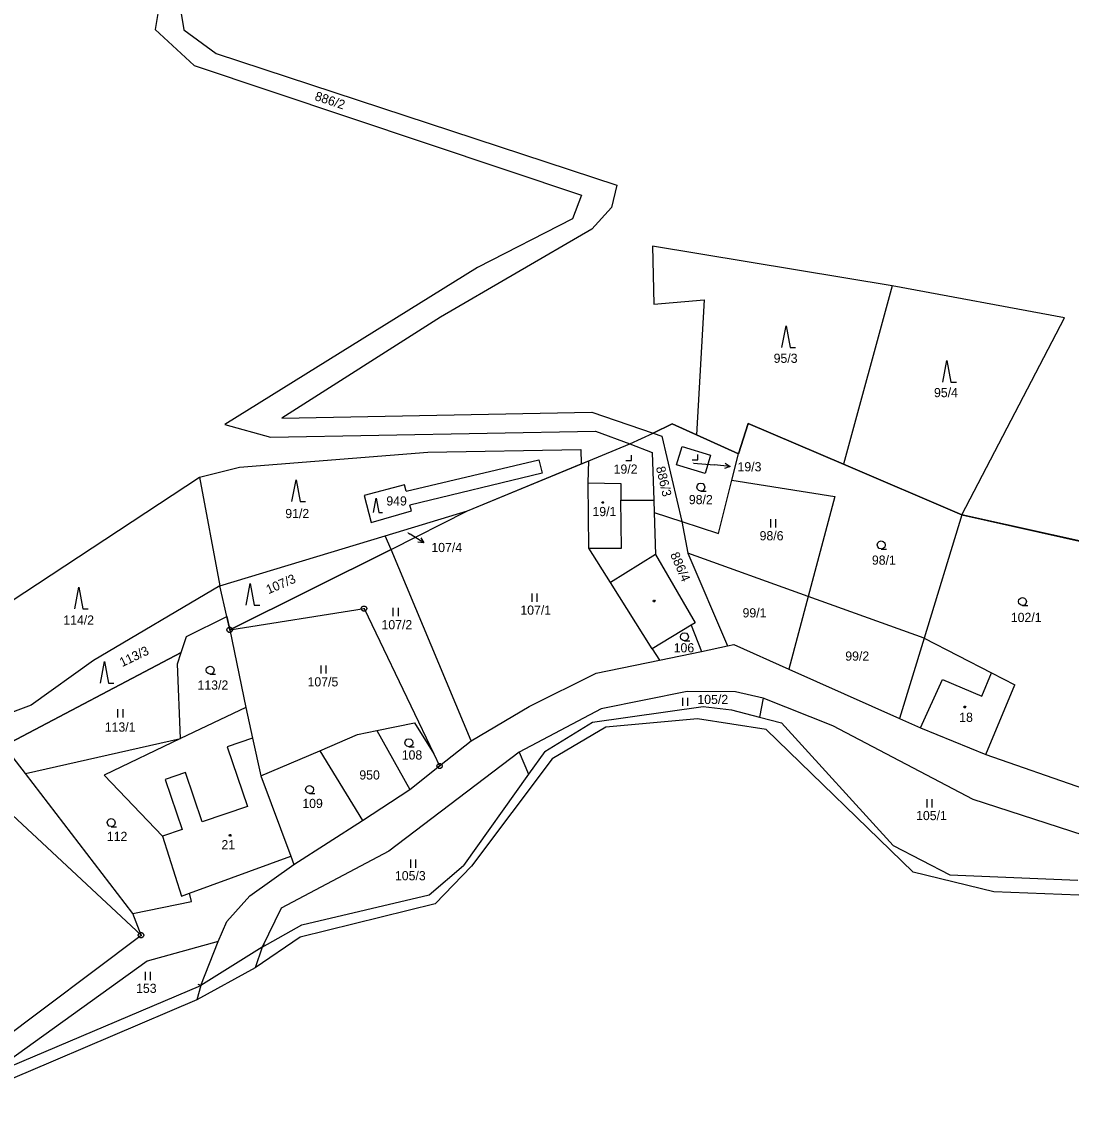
# Model space of a CAD drawing. Extents: x -580551 to -575069, y -1073031 to -1067931.
# Drawn here: x -576676.1 to -576481.9, y -1069876.2 to -1069674.8 of the extents above; entities that cross this region are included whole.
import ezdxf

# ---------------------------------------------------------------- set-up
doc = ezdxf.new("R2010")
doc.units = 0
for name, color, linetype in [('Druh pozemku', 7, 'Continuous'), ('Geodetické body', 7, 'Continuous'), ('Katastrální hranice', 7, 'Continuous'), ('Parcela', 7, 'Continuous'), ('Parcelní číslo', 7, 'Continuous'), ('Parcelní číslo_stavba', 7, 'Continuous'), ('Pomocná vrstva', 7, 'Continuous'), ('SR - hranice státu', 7, 'Continuous'), ('Vnitřní kresba', 7, 'Continuous'), ('Vrstva 26', 7, 'Continuous'), ('Vrstva 6', 7, 'Continuous')]:
    doc.layers.add(name, color=color, linetype=linetype)

msp = doc.modelspace()

# ---------------------------------------------------------------- linework, layer by layer
at = {"layer": 'Druh pozemku'}
for p, q in [((-576537.53, -1069766.84), (-576537.53, -1069768.34)), ((-576536.53, -1069768.34), (-576536.53, -1069766.84)), ((-576581.73, -1069780.59), (-576581.73, -1069782.09)), ((-576580.73, -1069782.09), (-576580.73, -1069780.59)), ((-576607.43, -1069783.24), (-576607.43, -1069784.74)), ((-576606.43, -1069784.74), (-576606.43, -1069783.24)), ((-576620.78, -1069793.89), (-576620.78, -1069795.39)), ((-576619.78, -1069795.39), (-576619.78, -1069793.89)), ((-576553.84, -1069799.85), (-576553.84, -1069801.35)), ((-576552.84, -1069801.35), (-576552.84, -1069799.85)), ((-576658.39, -1069802), (-576658.39, -1069803.5)), ((-576657.39, -1069803.5), (-576657.39, -1069802)), ((-576508.61, -1069818.65), (-576508.61, -1069820.15)), ((-576507.61, -1069820.15), (-576507.61, -1069818.65)), ((-576604.19, -1069829.8), (-576604.19, -1069831.3)), ((-576603.19, -1069831.3), (-576603.19, -1069829.8)), ((-576653.3, -1069850.6), (-576653.3, -1069852.1)), ((-576652.3, -1069852.1), (-576652.3, -1069850.6))]:
    msp.add_line(p, q, dxfattribs=at)
for points in [[(-576535.42, -1069735.03), (-576534.67, -1069731.03), (-576533.92, -1069735.03), (-576532.92, -1069735.03)], [(-576505.63, -1069741.44), (-576504.88, -1069737.44), (-576504.13, -1069741.44), (-576503.13, -1069741.44)], [(-576564.29, -1069755.94), (-576563.29, -1069755.94), (-576563.29, -1069754.94)], [(-576552.01, -1069755.82), (-576551.01, -1069755.82), (-576551.01, -1069754.82)], [(-576626.12, -1069763.52), (-576625.37, -1069759.52), (-576624.62, -1069763.52), (-576623.62, -1069763.52)], [(-576550.43, -1069761.62), (-576550.81, -1069761.52), (-576551.08, -1069761.25), (-576551.18, -1069760.88), (-576551.08, -1069760.51), (-576550.81, -1069760.24), (-576550.44, -1069760.14), (-576550.07, -1069760.24), (-576549.8, -1069760.51), (-576549.7, -1069760.89), (-576549.8, -1069761.27), (-576550.07, -1069761.54), (-576550.45, -1069761.64), (-576549.45, -1069761.64)], [(-576611.032, -1069765.58), (-576610.53, -1069762.9), (-576610.028, -1069765.58), (-576609.358, -1069765.58)], [(-576517.03, -1069772.33), (-576517.41, -1069772.23), (-576517.68, -1069771.96), (-576517.78, -1069771.59), (-576517.68, -1069771.22), (-576517.41, -1069770.95), (-576517.04, -1069770.85), (-576516.67, -1069770.95), (-576516.4, -1069771.22), (-576516.3, -1069771.6), (-576516.4, -1069771.98), (-576516.67, -1069772.25), (-576517.05, -1069772.35), (-576516.05, -1069772.35)], [(-576666.34, -1069783.39), (-576665.59, -1069779.39), (-576664.84, -1069783.39), (-576663.84, -1069783.39)], [(-576634.59, -1069782.74), (-576633.84, -1069778.74), (-576633.09, -1069782.74), (-576632.09, -1069782.74)], [(-576490.89, -1069782.79), (-576491.27, -1069782.69), (-576491.54, -1069782.42), (-576491.64, -1069782.05), (-576491.54, -1069781.68), (-576491.27, -1069781.41), (-576490.9, -1069781.31), (-576490.53, -1069781.41), (-576490.26, -1069781.68), (-576490.16, -1069782.06), (-576490.26, -1069782.44), (-576490.53, -1069782.71), (-576490.91, -1069782.81), (-576489.91, -1069782.81)], [(-576553.46, -1069789.31), (-576553.84, -1069789.21), (-576554.11, -1069788.94), (-576554.21, -1069788.57), (-576554.11, -1069788.2), (-576553.84, -1069787.93), (-576553.47, -1069787.83), (-576553.1, -1069787.93), (-576552.83, -1069788.2), (-576552.73, -1069788.58), (-576552.83, -1069788.96), (-576553.1, -1069789.23), (-576553.48, -1069789.33), (-576552.48, -1069789.33)], [(-576661.58, -1069797.17), (-576660.83, -1069793.17), (-576660.08, -1069797.17), (-576659.08, -1069797.17)], [(-576641.26, -1069795.49), (-576641.64, -1069795.39), (-576641.91, -1069795.12), (-576642.01, -1069794.75), (-576641.91, -1069794.38), (-576641.64, -1069794.11), (-576641.27, -1069794.01), (-576640.9, -1069794.11), (-576640.63, -1069794.38), (-576640.53, -1069794.76), (-576640.63, -1069795.14), (-576640.9, -1069795.41), (-576641.28, -1069795.51), (-576640.28, -1069795.51)], [(-576604.45, -1069808.92), (-576604.83, -1069808.82), (-576605.1, -1069808.55), (-576605.2, -1069808.18), (-576605.1, -1069807.81), (-576604.83, -1069807.54), (-576604.46, -1069807.44), (-576604.09, -1069807.54), (-576603.82, -1069807.81), (-576603.72, -1069808.19), (-576603.82, -1069808.57), (-576604.09, -1069808.84), (-576604.47, -1069808.94), (-576603.47, -1069808.94)], [(-576622.85, -1069817.58), (-576623.23, -1069817.48), (-576623.5, -1069817.21), (-576623.6, -1069816.84), (-576623.5, -1069816.47), (-576623.23, -1069816.2), (-576622.86, -1069816.1), (-576622.49, -1069816.2), (-576622.22, -1069816.47), (-576622.12, -1069816.85), (-576622.22, -1069817.23), (-576622.49, -1069817.5), (-576622.87, -1069817.6), (-576621.87, -1069817.6)], [(-576659.57, -1069823.71), (-576659.95, -1069823.61), (-576660.22, -1069823.34), (-576660.32, -1069822.97), (-576660.22, -1069822.6), (-576659.95, -1069822.33), (-576659.58, -1069822.23), (-576659.21, -1069822.33), (-576658.94, -1069822.6), (-576658.84, -1069822.98), (-576658.94, -1069823.36), (-576659.21, -1069823.63), (-576659.59, -1069823.73), (-576658.59, -1069823.73)]]:
    msp.add_lwpolyline(points, dxfattribs=at)
for points in [[(-576568.5, -1069763.58), (-576568.41, -1069763.73), (-576568.5, -1069763.88), (-576568.68, -1069763.88), (-576568.77, -1069763.73), (-576568.68, -1069763.58)], [(-576558.99, -1069781.83), (-576558.9, -1069781.98), (-576558.99, -1069782.13), (-576559.17, -1069782.13), (-576559.26, -1069781.98), (-576559.17, -1069781.83)], [(-576501.49, -1069801.42), (-576501.4, -1069801.57), (-576501.49, -1069801.72), (-576501.67, -1069801.72), (-576501.76, -1069801.57), (-576501.67, -1069801.42)], [(-576637.49, -1069825.15), (-576637.4, -1069825.3), (-576637.49, -1069825.45), (-576637.67, -1069825.45), (-576637.76, -1069825.3), (-576637.67, -1069825.15)]]:
    msp.add_lwpolyline(points, close=True, dxfattribs=at)
at = {"layer": 'Geodetické body'}
for p, q in [((-576612.9, -1069783.36), (-576612.66, -1069783.36)), ((-576637.77, -1069787.3), (-576637.53, -1069787.3)), ((-576598.92, -1069812.48), (-576598.68, -1069812.48)), ((-576654.17, -1069843.8), (-576653.93, -1069843.8))]:
    msp.add_line(p, q, dxfattribs=at)
for points in [[(-576612.63, -1069782.88), (-576612.38, -1069783.06), (-576612.28, -1069783.35), (-576612.38, -1069783.64), (-576612.63, -1069783.82), (-576612.94, -1069783.82), (-576613.19, -1069783.64), (-576613.29, -1069783.35), (-576613.19, -1069783.06), (-576612.94, -1069782.88)], [(-576637.5, -1069786.82), (-576637.25, -1069787), (-576637.15, -1069787.29), (-576637.25, -1069787.58), (-576637.5, -1069787.76), (-576637.81, -1069787.76), (-576638.06, -1069787.58), (-576638.16, -1069787.29), (-576638.06, -1069787), (-576637.81, -1069786.82)], [(-576598.65, -1069812), (-576598.4, -1069812.18), (-576598.3, -1069812.47), (-576598.4, -1069812.76), (-576598.65, -1069812.94), (-576598.96, -1069812.94), (-576599.21, -1069812.76), (-576599.31, -1069812.47), (-576599.21, -1069812.18), (-576598.96, -1069812)], [(-576653.9, -1069843.32), (-576653.65, -1069843.5), (-576653.55, -1069843.79), (-576653.65, -1069844.08), (-576653.9, -1069844.26), (-576654.21, -1069844.26), (-576654.46, -1069844.08), (-576654.56, -1069843.79), (-576654.46, -1069843.5), (-576654.21, -1069843.32)]]:
    msp.add_lwpolyline(points, close=True, dxfattribs=at)
at = {"layer": 'Katastrální hranice'}
for p, q in [((-576551.03, -1069803.75), (-576568.02, -1069805.29)), ((-576538.37, -1069805.74), (-576551.03, -1069803.75)), ((-576568.02, -1069805.29), (-576577.93, -1069811.18)), ((-576511.13, -1069832.12), (-576538.37, -1069805.74)), ((-576577.93, -1069811.18), (-576592.88, -1069831.04)), ((-576592.88, -1069831.04), (-576599.63, -1069837.99)), ((-576496.21, -1069835.74), (-576511.13, -1069832.12)), ((-576476.91, -1069836.55), (-576496.21, -1069835.74)), ((-576599.63, -1069837.99), (-576624.59, -1069844.18)), ((-576624.59, -1069844.18), (-576632.96, -1069849.85)), ((-576632.96, -1069849.85), (-576643.76, -1069855.73)), ((-576643.76, -1069855.73), (-576674.95, -1069869.1)), ((-576674.95, -1069869.1), (-576691.8, -1069876.18))]:
    msp.add_line(p, q, dxfattribs=at)
at = {"layer": 'Parcela'}
for p, q in [((-576647.31, -1069651.23), (-576651.43, -1069676.21)), ((-576647.17, -1069669.99), (-576646.13, -1069676.24)), ((-576651.43, -1069676.21), (-576644.23, -1069682.85)), ((-576646.13, -1069676.24), (-576640.16, -1069680.67)), ((-576640.16, -1069680.67), (-576565.99, -1069705.03)), ((-576644.23, -1069682.85), (-576572.5, -1069706.89)), ((-576565.99, -1069705.03), (-576566.97, -1069709.17)), ((-576572.5, -1069706.89), (-576574.2, -1069711.27)), ((-576566.97, -1069709.17), (-576570.63, -1069713.15)), ((-576574.2, -1069711.27), (-576591.75, -1069720.23)), ((-576570.63, -1069713.15), (-576598.6, -1069729.46)), ((-576591.75, -1069720.23), (-576638.57, -1069749.29)), ((-576598.6, -1069729.46), (-576627.99, -1069748.15)), ((-576627.99, -1069748.15), (-576570.63, -1069747)), ((-576570.63, -1069747), (-576559.28, -1069750.92)), ((-576638.57, -1069749.29), (-576630.1, -1069751.65)), ((-576555.75, -1069749.15), (-576559.28, -1069750.92)), ((-576551.25, -1069751.2), (-576555.75, -1069749.15)), ((-576541.66, -1069749.1), (-576543.46, -1069754.74)), ((-576524, -1069756.64), (-576541.66, -1069749.1)), ((-576630.1, -1069751.65), (-576569.94, -1069750.52)), ((-576569.94, -1069750.52), (-576563.6, -1069752.9)), ((-576563.6, -1069752.9), (-576559.28, -1069750.92)), ((-576559.28, -1069750.92), (-576557.63, -1069751.47)), ((-576557.63, -1069751.47), (-576553.98, -1069767.25)), ((-576543.46, -1069754.74), (-576551.25, -1069751.2)), ((-576571.19, -1069756.02), (-576563.6, -1069752.9)), ((-576563.6, -1069752.9), (-576559.45, -1069754.48)), ((-576554.93, -1069756.79), (-576553.91, -1069753.35)), ((-576553.91, -1069753.35), (-576548.66, -1069754.94)), ((-576559.45, -1069754.48), (-576559.15, -1069763.27)), ((-576548.66, -1069754.94), (-576549.61, -1069758.38)), ((-576544.68, -1069759.61), (-576543.46, -1069754.74)), ((-576604.99, -1069761.66), (-576580.4, -1069755.83)), ((-576593.62, -1069765.25), (-576572.58, -1069756.59)), ((-576580.4, -1069755.83), (-576579.83, -1069758.3)), ((-576572.58, -1069756.59), (-576571.19, -1069756.02)), ((-576571.3, -1069760.08), (-576571.19, -1069756.02)), ((-576549.61, -1069758.38), (-576554.93, -1069756.79)), ((-576502.1, -1069766), (-576524, -1069756.64)), ((-576694.77, -1069792.96), (-576643.26, -1069759.05)), ((-576643.26, -1069759.05), (-576639.47, -1069779.16)), ((-576579.83, -1069758.3), (-576604.29, -1069764.24)), ((-576547.14, -1069769.46), (-576544.68, -1069759.61)), ((-576544.68, -1069759.61), (-576525.62, -1069762.59)), ((-576605.31, -1069760.48), (-576612.77, -1069762.42)), ((-576604.99, -1069761.66), (-576605.31, -1069760.48)), ((-576571.3, -1069760.08), (-576565.25, -1069760.21)), ((-576571.16, -1069772.17), (-576571.3, -1069760.08)), ((-576565.25, -1069760.21), (-576565.22, -1069763.28)), ((-576612.77, -1069762.42), (-576611.45, -1069767.46)), ((-576565.22, -1069763.28), (-576559.15, -1069763.27)), ((-576559.15, -1069763.27), (-576559.07, -1069765.6)), ((-576525.62, -1069762.59), (-576530.55, -1069781.12)), ((-576611.45, -1069767.46), (-576604.01, -1069765.29)), ((-576608.86, -1069769.87), (-576593.62, -1069765.25)), ((-576607.77, -1069772.42), (-576593.62, -1069765.25)), ((-576604.01, -1069765.29), (-576604.29, -1069764.24)), ((-576559.07, -1069765.6), (-576558.81, -1069773.32)), ((-576559.07, -1069765.6), (-576553.98, -1069767.25)), ((-576553.98, -1069767.25), (-576547.14, -1069769.46)), ((-576553.98, -1069767.25), (-576552.83, -1069773.1)), ((-576502.1, -1069766), (-576509.09, -1069788.84)), ((-576473.99, -1069772.28), (-576502.1, -1069766)), ((-576639.47, -1069779.16), (-576608.86, -1069769.87)), ((-576607.77, -1069772.42), (-576608.86, -1069769.87)), ((-576607.77, -1069772.42), (-576637.65, -1069787.3)), ((-576592.96, -1069807.81), (-576607.77, -1069772.42)), ((-576567.14, -1069778.55), (-576571.16, -1069772.17)), ((-576558.81, -1069773.32), (-576551.5, -1069785.98)), ((-576552.83, -1069773.1), (-576545.53, -1069790.28)), ((-576530.55, -1069781.12), (-576552.83, -1069773.1)), ((-576639.47, -1069779.16), (-576662.88, -1069792.95)), ((-576638.2, -1069784.83), (-576639.47, -1069779.16)), ((-576559.42, -1069790.82), (-576567.14, -1069778.55)), ((-576530.55, -1069781.12), (-576534.13, -1069794.57)), ((-576509.09, -1069788.84), (-576530.55, -1069781.12)), ((-576637.65, -1069787.3), (-576612.78, -1069783.36)), ((-576612.78, -1069783.36), (-576602.71, -1069804.34)), ((-576645.63, -1069788.55), (-576638.2, -1069784.83)), ((-576637.65, -1069787.3), (-576638.2, -1069784.83)), ((-576637.65, -1069787.3), (-576634.69, -1069801.68)), ((-576552.24, -1069786.43), (-576559.42, -1069790.82)), ((-576551.5, -1069785.98), (-576552.24, -1069786.43)), ((-576552.24, -1069786.43), (-576550.31, -1069791.28)), ((-576646.62, -1069791.48), (-576645.63, -1069788.55)), ((-576509.09, -1069788.84), (-576513.64, -1069803.7)), ((-576509.09, -1069788.84), (-576496.62, -1069795.25)), ((-576646.62, -1069791.48), (-576679.38, -1069808.74)), ((-576647.33, -1069793.56), (-576646.62, -1069791.48)), ((-576559.42, -1069790.82), (-576558.11, -1069792.9)), ((-576558.11, -1069792.9), (-576550.31, -1069791.28)), ((-576550.31, -1069791.28), (-576545.53, -1069790.28)), ((-576545.53, -1069790.28), (-576544.31, -1069790.03)), ((-576544.31, -1069790.03), (-576534.13, -1069794.57)), ((-576662.88, -1069792.95), (-576674.38, -1069801.23)), ((-576646.75, -1069807.42), (-576647.33, -1069793.56)), ((-576569.83, -1069795.33), (-576558.11, -1069792.9)), ((-576582.24, -1069801.48), (-576569.83, -1069795.33)), ((-576534.13, -1069794.57), (-576513.64, -1069803.7)), ((-576496.62, -1069795.25), (-576492.32, -1069797.46)), ((-576497.69, -1069810.33), (-576492.32, -1069797.46)), ((-576552.97, -1069798.73), (-576568.88, -1069801.88)), ((-576543.99, -1069798.79), (-576552.97, -1069798.73)), ((-576538.89, -1069799.91), (-576543.99, -1069798.79)), ((-576538.89, -1069799.91), (-576539.57, -1069803.42)), ((-576525.98, -1069805.05), (-576538.89, -1069799.91)), ((-576674.38, -1069801.23), (-576682.77, -1069804.33)), ((-576634.69, -1069801.68), (-576646.75, -1069807.42)), ((-576634.69, -1069801.68), (-576633.44, -1069807.32)), ((-576592.96, -1069807.81), (-576582.24, -1069801.48)), ((-576568.88, -1069801.88), (-576584.05, -1069809.91)), ((-576570.51, -1069804.35), (-576550.02, -1069801.5)), ((-576550.02, -1069801.5), (-576544.73, -1069802.09)), ((-576544.73, -1069802.09), (-576539.57, -1069803.42)), ((-576539.57, -1069803.42), (-576535.51, -1069804.47)), ((-576513.64, -1069803.7), (-576509.79, -1069805.42)), ((-576614.01, -1069806.67), (-576610.41, -1069805.93)), ((-576610.41, -1069805.93), (-576603.44, -1069804.5)), ((-576610.41, -1069805.93), (-576604.3, -1069816.84)), ((-576603.44, -1069804.5), (-576599.88, -1069810.23)), ((-576602.71, -1069804.34), (-576599.88, -1069810.23)), ((-576579.3, -1069809.79), (-576570.51, -1069804.35)), ((-576535.51, -1069804.47), (-576514.84, -1069827.18)), ((-576500.03, -1069818.69), (-576525.98, -1069805.05)), ((-576509.79, -1069805.42), (-576497.69, -1069810.33)), ((-576675.42, -1069813.89), (-576646.75, -1069807.42)), ((-576646.75, -1069807.42), (-576660.9, -1069814.16)), ((-576633.44, -1069807.32), (-576631.9, -1069814.32)), ((-576620.98, -1069809.65), (-576614.01, -1069806.67)), ((-576598.8, -1069812.48), (-576592.96, -1069807.81)), ((-576675.42, -1069813.89), (-576679.38, -1069808.74)), ((-576631.9, -1069814.32), (-576620.98, -1069809.65)), ((-576620.98, -1069809.65), (-576613.05, -1069822.55)), ((-576584.05, -1069809.91), (-576608.17, -1069828.27)), ((-576584.05, -1069809.91), (-576582.32, -1069814.01)), ((-576579.3, -1069809.79), (-576582.32, -1069814.01)), ((-576599.88, -1069810.23), (-576598.8, -1069812.48)), ((-576497.69, -1069810.33), (-576479.58, -1069816.65)), ((-576655.55, -1069839.76), (-576675.42, -1069813.89)), ((-576604.3, -1069816.84), (-576598.8, -1069812.48)), ((-576582.32, -1069814.01), (-576594.39, -1069830.9)), ((-576685.23, -1069814.74), (-576654.05, -1069843.8)), ((-576660.9, -1069814.16), (-576650.11, -1069825.48)), ((-576631.9, -1069814.32), (-576626.34, -1069829.19)), ((-576613.05, -1069822.55), (-576604.3, -1069816.84)), ((-576479.69, -1069825.3), (-576500.03, -1069818.69)), ((-576625.78, -1069830.69), (-576613.05, -1069822.55)), ((-576650.11, -1069825.48), (-576646.55, -1069836.55)), ((-576514.84, -1069827.18), (-576504.35, -1069832.65)), ((-576645.09, -1069836.02), (-576626.34, -1069829.19)), ((-576608.17, -1069828.27), (-576628.11, -1069838.81)), ((-576626.34, -1069829.19), (-576625.78, -1069830.69)), ((-576633.9, -1069836.5), (-576625.78, -1069830.69)), ((-576600.72, -1069836.32), (-576594.39, -1069830.9)), ((-576504.35, -1069832.65), (-576480.63, -1069833.61)), ((-576646.55, -1069836.55), (-576645.09, -1069836.02)), ((-576644.7, -1069837.57), (-576645.09, -1069836.02)), ((-576655.55, -1069839.76), (-576644.7, -1069837.57)), ((-576638.18, -1069841.27), (-576633.9, -1069836.5)), ((-576624.3, -1069841.86), (-576600.72, -1069836.32)), ((-576654.05, -1069843.8), (-576655.55, -1069839.76)), ((-576628.11, -1069838.81), (-576631.65, -1069846.02)), ((-576639.77, -1069844.94), (-576638.18, -1069841.27)), ((-576631.65, -1069846.02), (-576624.3, -1069841.86)), ((-576681.56, -1069864.43), (-576654.05, -1069843.8)), ((-576639.77, -1069844.94), (-576652.95, -1069848.59)), ((-576643.02, -1069853.07), (-576639.77, -1069844.94)), ((-576631.65, -1069846.02), (-576643.02, -1069853.07)), ((-576652.95, -1069848.59), (-576682.48, -1069869.82)), ((-576682.48, -1069869.82), (-576643.02, -1069853.07))]:
    msp.add_line(p, q, dxfattribs=at)
at = {"layer": 'Pomocná vrstva'}
for p, q in [((-576551.81, -1069756.43), (-576547.98, -1069756.77)), ((-576544.992, -1069757.041), (-576547.98, -1069756.77)), ((-576604.59, -1069769.35), (-576604.23, -1069769.58)), ((-576601.707, -1069771.202), (-576604.23, -1069769.58))]:
    msp.add_line(p, q, dxfattribs=at)
for points in [[(-576545.943, -1069756.453), (-576544.992, -1069757.041), (-576546.033, -1069757.448)], [(-576602.277, -1069770.241), (-576601.707, -1069771.202), (-576602.818, -1069771.082)]]:
    msp.add_lwpolyline(points, dxfattribs=at)
at = {"layer": 'SR - hranice státu'}
for points in [[(-576563.6, -1069752.9), (-576559.28, -1069750.92), (-576555.75, -1069749.15), (-576543.46, -1069754.74), (-576541.66, -1069749.1), (-576524, -1069756.64), (-576502.1, -1069766)], [(-576637.65, -1069787.3), (-576607.77, -1069772.42), (-576593.62, -1069765.25), (-576571.19, -1069756.02), (-576563.6, -1069752.9)], [(-576502.1, -1069766), (-576473.99, -1069772.28), (-576472.56, -1069754.29), (-576437.96, -1069761.31), (-576424.84, -1069760.69)], [(-576679.38, -1069808.74), (-576646.62, -1069791.48), (-576645.63, -1069788.55), (-576638.2, -1069784.83), (-576637.65, -1069787.3)]]:
    msp.add_lwpolyline(points, dxfattribs=at)
at = {"layer": 'Vnitřní kresba'}
for p, q in [((-576565.15, -1069772.18), (-576565.22, -1069763.28)), ((-576571.16, -1069772.17), (-576565.15, -1069772.18)), ((-576558.81, -1069773.32), (-576567.14, -1069778.55)), ((-576498.44, -1069799.57), (-576496.62, -1069795.25)), ((-576509.79, -1069805.42), (-576505.7, -1069796.46)), ((-576505.7, -1069796.46), (-576498.44, -1069799.57)), ((-576633.44, -1069807.32), (-576638.11, -1069808.91)), ((-576638.11, -1069808.91), (-576634.36, -1069819.95)), ((-576645.83, -1069813.69), (-576649.57, -1069814.96)), ((-576642.74, -1069822.79), (-576645.83, -1069813.69)), ((-576649.57, -1069814.96), (-576646.43, -1069824.24)), ((-576634.36, -1069819.95), (-576642.74, -1069822.79)), ((-576646.43, -1069824.24), (-576650.11, -1069825.48)), ((-576631.65, -1069846.02), (-576632.96, -1069849.85)), ((-576643.02, -1069853.07), (-576643.76, -1069855.73))]:
    msp.add_line(p, q, dxfattribs=at)
at = {"layer": 'Vrstva 26'}
for p, q in [((-576631.65, -1069846.02), (-576631.196, -1069845.478)), ((-576643.02, -1069853.07), (-576643.464, -1069852.904))]:
    msp.add_line(p, q, dxfattribs=at)
at = {"layer": 'Vrstva 6'}
for p, q in [((-576515.03, -1069723.62), (-576559.37, -1069716.29)), ((-576559.37, -1069716.29), (-576559.11, -1069727)), ((-576515.03, -1069723.62), (-576524, -1069756.64)), ((-576483.11, -1069729.57), (-576515.03, -1069723.62)), ((-576559.11, -1069727), (-576549.8, -1069726.24)), ((-576549.8, -1069726.24), (-576551.25, -1069751.2)), ((-576502.1, -1069766), (-576483.11, -1069729.57)), ((-576635.85, -1069757.17), (-576600.97, -1069754.39)), ((-576600.97, -1069754.39), (-576572.66, -1069753.9)), ((-576572.66, -1069753.9), (-576572.58, -1069756.59)), ((-576643.26, -1069759.05), (-576635.85, -1069757.17))]:
    msp.add_line(p, q, dxfattribs=at)

# ---------------------------------------------------------------- texts
at = {"layer": 'Parcelní číslo'}
for s, rotation, p in [('886/2', 341.54014, (-576622.04, -1069689.225)), ('886/3', 283.04115, (-576558.752, -1069757.238)), ('886/4', 293.58357, (-576556.141, -1069773.351)), ('107/3', 23.37668, (-576630.468, -1069780.716)), ('113/3', 25.55392, (-576657.557, -1069794.198))]:
    msp.add_text(s, height=1.7, rotation=rotation, dxfattribs=at).set_placement(p)
for s, height, p in [('95/3', 1.7, (-576536.959, -1069737.89)), ('95/4', 1.7, (-576507.272, -1069744.24)), ('949', 1.7, (-576608.644, -1069764.29)), ('98/2', 1.7, (-576552.65, -1069764.04)), ('91/2', 1.7, (-576627.359, -1069766.62)), ('107/4', 0.1, (-576604.771, -1069769.35)), ('98/6', 1.7, (-576539.555, -1069770.73)), ('98/1', 1.7, (-576518.768, -1069775.24)), ('107/1', 1.7, (-576583.843, -1069784.49)), ('99/1', 1.7, (-576542.714, -1069784.99)), ('114/2', 1.7, (-576668.45, -1069786.33)), ('107/2', 1.7, (-576609.545, -1069787.19)), ('102/1', 1.7, (-576493.054, -1069785.84)), ('106', 1.7, (-576555.461, -1069791.46)), ('99/2', 1.7, (-576523.696, -1069793)), ('107/5', 1.7, (-576623.232, -1069797.76)), ('113/2', 1.7, (-576643.597, -1069798.36)), ('105/2', 1.7, (-576551.072, -1069801.02)), ('113/1', 1.7, (-576660.775, -1069806.13)), ('108', 1.7, (-576605.799, -1069811.29)), ('950', 1.7, (-576613.649, -1069814.99)), ('109', 1.7, (-576624.201, -1069820.26)), ('105/1', 1.7, (-576510.59, -1069822.5)), ('112', 1.7, (-576660.385, -1069826.36)), ('105/3', 1.7, (-576607.054, -1069833.63)), ('153', 1.7, (-576654.975, -1069854.47))]:
    msp.add_text(s, height=height, dxfattribs=at).set_placement(p)
at = {"layer": 'Parcelní číslo_stavba'}
for s, height, p in [('19/2', 1.7, (-576566.579, -1069758.4)), ('19/3', 0.1, (-576551.956, -1069756.43)), ('19/1', 1.7, (-576570.497, -1069766.25)), ('18', 1.7, (-576502.607, -1069804.32)), ('21', 1.7, (-576639.174, -1069827.9))]:
    msp.add_text(s, height=height, dxfattribs=at).set_placement(p)
at = {"layer": 'Pomocná vrstva'}
for s, p in [('19/3', (-576543.641, -1069757.97)), ('107/4', (-576600.317, -1069772.9))]:
    msp.add_text(s, height=1.7, dxfattribs=at).set_placement(p)

doc.saveas('drawing.dxf')
